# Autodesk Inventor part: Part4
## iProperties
Shininess: 64.0
Length Units: 11269
Angle Units: 11279
Time Units: 11290
Mass Units: 11283
Length Display Precision: 3
Angle Display Precision: 2
Compacted: True
Part Number: Part4
Document SubType Name: Modeling
Created: 2002-12
Designer: deepak
Density: 0.0
Volumn: 0.0
Area: 0.0
PropertySet Name: Model Information
Control State: 0
Master: False
Checked Out: False
Author: deepak
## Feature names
1. Extrusion1
2. Split1
